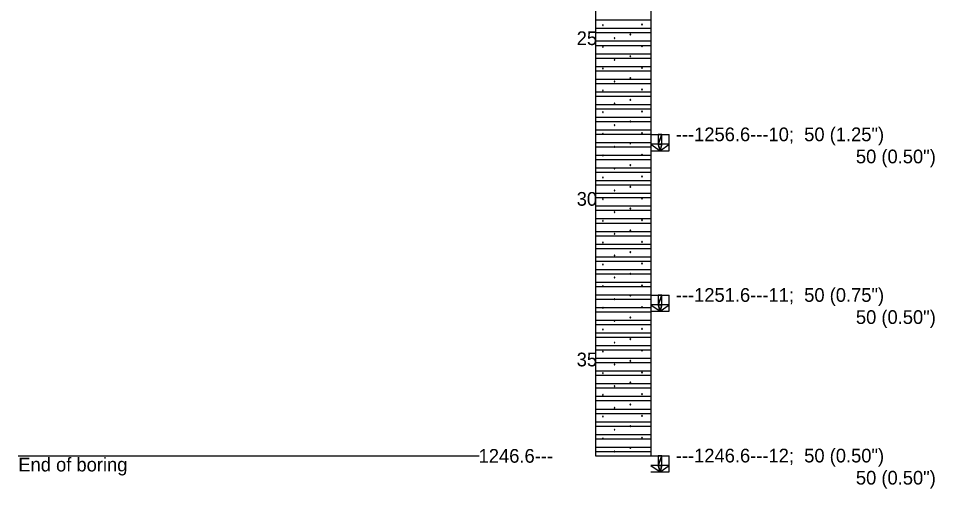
# Model space of a CAD drawing. Extents: x 7 to 126, y 24 to 56.
# Drawn here: x 69.7 to 77.99, y 38.85 to 43.11 of the extents above; entities that cross this region are included whole.
import ezdxf

# ---------------------------------------------------------------- set-up
doc = ezdxf.new("R2010")
doc.units = 0

msp = doc.modelspace()

# ---------------------------------------------------------------- linework, layer by layer
for points in [[(74.9215, 50.1944), (74.9215, 39.1479)], [(75.4215, 50.1944), (75.4215, 39.1479)], [(74.9215, 43.0925), (75.4215, 43.0925)], [(74.9215, 43.017), (75.4215, 43.017)], [(74.9919, 43.0463), (74.9902, 43.0491), (74.9869, 43.0491), (74.9853, 43.0463), (74.9869, 43.0434), (74.9902, 43.0434), (74.9919, 43.0463)], [(75.3446, 43.0528), (75.343, 43.0557), (75.3397, 43.0557), (75.3381, 43.0528), (75.3397, 43.0499), (75.343, 43.0499), (75.3446, 43.0528)], [(74.9215, 42.9776), (75.4215, 42.9776)], [(75.0965, 42.9284), (75.0949, 42.9312), (75.0916, 42.9312), (75.09, 42.9284), (75.0916, 42.9255), (75.0949, 42.9255), (75.0965, 42.9284)], [(75.2391, 42.9602), (75.2375, 42.9631), (75.2342, 42.9631), (75.2326, 42.9602), (75.2342, 42.9574), (75.2375, 42.9574), (75.2391, 42.9602)], [(74.9215, 42.9022), (75.4215, 42.9022)], [(74.9215, 42.8628), (75.4215, 42.8628)], [(74.9919, 42.8494), (74.9902, 42.8522), (74.9869, 42.8522), (74.9853, 42.8494), (74.9869, 42.8465), (74.9902, 42.8465), (74.9919, 42.8494)], [(75.3446, 42.8559), (75.343, 42.8588), (75.3397, 42.8588), (75.3381, 42.8559), (75.3397, 42.8531), (75.343, 42.8531), (75.3446, 42.8559)], [(74.9215, 42.7873), (75.4215, 42.7873)], [(75.2391, 42.7634), (75.2375, 42.7662), (75.2342, 42.7662), (75.2326, 42.7634), (75.2342, 42.7606), (75.2375, 42.7606), (75.2391, 42.7634)], [(74.9215, 42.748), (75.4215, 42.748)], [(74.9215, 42.6725), (75.4215, 42.6725)], [(75.0965, 42.7315), (75.0949, 42.7344), (75.0916, 42.7344), (75.09, 42.7316), (75.0916, 42.7287), (75.0949, 42.7287), (75.0965, 42.7315)], [(74.9215, 42.6331), (75.4215, 42.6331)], [(74.9919, 42.6526), (74.9902, 42.6554), (74.9869, 42.6554), (74.9853, 42.6526), (74.9869, 42.6497), (74.9902, 42.6497), (74.9919, 42.6526)], [(75.3446, 42.6591), (75.343, 42.662), (75.3397, 42.662), (75.3381, 42.6591), (75.3397, 42.6562), (75.343, 42.6562), (75.3446, 42.6591)], [(74.9215, 42.5577), (75.4215, 42.5577)], [(74.9215, 42.5183), (75.4215, 42.5183)], [(75.0965, 42.5347), (75.0949, 42.5375), (75.0916, 42.5375), (75.09, 42.5347), (75.0916, 42.5318), (75.0949, 42.5318), (75.0965, 42.5347)], [(75.2391, 42.5665), (75.2375, 42.5694), (75.2342, 42.5694), (75.2326, 42.5665), (75.2342, 42.5637), (75.2375, 42.5637), (75.2391, 42.5665)], [(74.9215, 42.4429), (75.4215, 42.4429)], [(74.9919, 42.4557), (74.9902, 42.4585), (74.9869, 42.4585), (74.9853, 42.4557), (74.9869, 42.4528), (74.9902, 42.4528), (74.9919, 42.4557)], [(75.3446, 42.4622), (75.343, 42.4651), (75.3397, 42.4651), (75.3381, 42.4622), (75.3397, 42.4594), (75.343, 42.4594), (75.3446, 42.4622)], [(74.9215, 42.4035), (75.4215, 42.4035)], [(75.0965, 42.3378), (75.0949, 42.3407), (75.0916, 42.3407), (75.09, 42.3379), (75.0916, 42.335), (75.0949, 42.335), (75.0965, 42.3378)], [(75.2391, 42.3697), (75.2375, 42.3725), (75.2342, 42.3725), (75.2326, 42.3697), (75.2342, 42.3669), (75.2375, 42.3669), (75.2391, 42.3697)], [(74.9215, 42.328), (75.4215, 42.328)], [(74.9215, 42.2887), (75.4215, 42.2887)], [(74.9919, 42.2589), (74.9902, 42.2617), (74.9869, 42.2617), (74.9853, 42.2589), (74.9869, 42.256), (74.9902, 42.256), (74.9919, 42.2589)], [(75.3446, 42.2654), (75.343, 42.2682), (75.3397, 42.2682), (75.3381, 42.2654), (75.3397, 42.2625), (75.343, 42.2625), (75.3446, 42.2654)], [(74.9215, 42.2132), (75.4215, 42.2132)], [(74.9215, 42.1738), (75.4215, 42.1738)], [(75.2391, 42.1728), (75.2375, 42.1757), (75.2342, 42.1757), (75.2326, 42.1728), (75.2342, 42.17), (75.2375, 42.17), (75.2391, 42.1728)], [(74.9215, 42.0984), (75.4215, 42.0984)], [(75.0965, 42.141), (75.0949, 42.1438), (75.0916, 42.1438), (75.09, 42.141), (75.0916, 42.1381), (75.0949, 42.1381), (75.0965, 42.141)], [(74.9215, 42.059), (75.4215, 42.059)], [(74.9919, 42.062), (74.9902, 42.0648), (74.9869, 42.0648), (74.9853, 42.062), (74.9869, 42.0591), (74.9902, 42.0591), (74.9919, 42.062)], [(75.3446, 42.0685), (75.343, 42.0714), (75.3397, 42.0714), (75.3381, 42.0685), (75.3397, 42.0657), (75.343, 42.0657), (75.3446, 42.0685)], [(75.4215, 42.0549), (75.5881, 42.0549)], [(75.5881, 41.9095), (75.5881, 42.0549)], [(74.9215, 41.9835), (75.4215, 41.9835)], [(74.9215, 41.9442), (75.4215, 41.9442)], [(75.0965, 41.9441), (75.0949, 41.947), (75.0916, 41.947), (75.09, 41.9442), (75.0916, 41.9413), (75.0949, 41.9413), (75.0965, 41.9441)], [(75.2391, 41.976), (75.2375, 41.9788), (75.2342, 41.9788), (75.2326, 41.976), (75.2342, 41.9732), (75.2375, 41.9732), (75.2391, 41.976)], [(74.9215, 41.8687), (75.4215, 41.8687)], [(74.9919, 41.8652), (74.9902, 41.868), (74.9869, 41.868), (74.9853, 41.8652), (74.9869, 41.8623), (74.9902, 41.8623), (74.9919, 41.8652)], [(75.3446, 41.8717), (75.343, 41.8745), (75.3397, 41.8745), (75.3381, 41.8717), (75.3397, 41.8688), (75.343, 41.8688), (75.3446, 41.8717)], [(75.4215, 41.9095), (75.5881, 41.9095)], [(74.9215, 41.8293), (75.4215, 41.8293)], [(75.2391, 41.7791), (75.2375, 41.782), (75.2342, 41.782), (75.2326, 41.7791), (75.2342, 41.7763), (75.2375, 41.7763), (75.2391, 41.7791)], [(74.9215, 41.7539), (75.4215, 41.7539)], [(74.9215, 41.7145), (75.4215, 41.7145)], [(75.0965, 41.7473), (75.0949, 41.7501), (75.0916, 41.7501), (75.09, 41.7473), (75.0916, 41.7444), (75.0949, 41.7444), (75.0965, 41.7473)], [(75.3446, 41.6748), (75.343, 41.6777), (75.3397, 41.6777), (75.3381, 41.6748), (75.3397, 41.672), (75.343, 41.672), (75.3446, 41.6748)], [(74.9215, 41.6391), (75.4215, 41.6391)], [(74.9215, 41.5997), (75.4215, 41.5997)], [(74.9919, 41.6683), (74.9902, 41.6711), (74.9869, 41.6711), (74.9853, 41.6683), (74.9869, 41.6654), (74.9902, 41.6654), (74.9919, 41.6683)], [(74.9215, 41.5242), (75.4215, 41.5242)], [(75.0965, 41.5504), (75.0949, 41.5533), (75.0916, 41.5533), (75.09, 41.5505), (75.0916, 41.5476), (75.0949, 41.5476), (75.0965, 41.5504)], [(75.2391, 41.5823), (75.2375, 41.5851), (75.2342, 41.5851), (75.2326, 41.5823), (75.2342, 41.5795), (75.2375, 41.5795), (75.2391, 41.5823)], [(74.9215, 41.4849), (75.4215, 41.4849)], [(74.9919, 41.4715), (74.9902, 41.4743), (74.9869, 41.4743), (74.9853, 41.4715), (74.9869, 41.4686), (74.9902, 41.4686), (74.9919, 41.4715)], [(75.3446, 41.478), (75.343, 41.4808), (75.3397, 41.4808), (75.3381, 41.478), (75.3397, 41.4751), (75.343, 41.4751), (75.3446, 41.478)], [(74.9215, 41.4094), (75.4215, 41.4094)], [(74.9215, 41.37), (75.4215, 41.37)], [(75.0965, 41.3536), (75.0949, 41.3564), (75.0916, 41.3564), (75.09, 41.3536), (75.0916, 41.3507), (75.0949, 41.3507), (75.0965, 41.3536)], [(75.2391, 41.3854), (75.2375, 41.3883), (75.2342, 41.3883), (75.2326, 41.3854), (75.2342, 41.3826), (75.2375, 41.3826), (75.2391, 41.3854)], [(74.9215, 41.2946), (75.4215, 41.2946)], [(74.9919, 41.2746), (74.9902, 41.2774), (74.9869, 41.2774), (74.9853, 41.2746), (74.9869, 41.2717), (74.9902, 41.2717), (74.9919, 41.2746)], [(75.3446, 41.2811), (75.343, 41.284), (75.3397, 41.284), (75.3381, 41.2811), (75.3397, 41.2783), (75.343, 41.2783), (75.3446, 41.2811)], [(74.9215, 41.2552), (75.4215, 41.2552)], [(74.9215, 41.1797), (75.4215, 41.1797)], [(75.2391, 41.1886), (75.2375, 41.1914), (75.2342, 41.1914), (75.2326, 41.1886), (75.2342, 41.1858), (75.2375, 41.1858), (75.2391, 41.1886)], [(74.9215, 41.1404), (75.4215, 41.1404)], [(75.0965, 41.1567), (75.0949, 41.1596), (75.0916, 41.1596), (75.09, 41.1568), (75.0916, 41.1539), (75.0949, 41.1539), (75.0965, 41.1567)], [(74.9215, 41.0649), (75.4215, 41.0649)], [(74.9215, 41.0255), (75.4215, 41.0255)], [(74.9919, 41.0778), (74.9902, 41.0806), (74.9869, 41.0806), (74.9853, 41.0778), (74.9869, 41.0749), (74.9902, 41.0749), (74.9919, 41.0778)], [(75.3446, 41.0843), (75.343, 41.0871), (75.3397, 41.0871), (75.3381, 41.0843), (75.3397, 41.0814), (75.343, 41.0814), (75.3446, 41.0843)], [(74.9215, 40.9501), (75.4215, 40.9501)], [(75.0965, 40.9599), (75.0949, 40.9627), (75.0916, 40.9627), (75.09, 40.9599), (75.0916, 40.957), (75.0949, 40.957), (75.0965, 40.9599)], [(75.2391, 40.9917), (75.2375, 40.9946), (75.2342, 40.9946), (75.2326, 40.9917), (75.2342, 40.9889), (75.2375, 40.9889), (75.2391, 40.9917)], [(74.9215, 40.9107), (75.4215, 40.9107)], [(74.9919, 40.8809), (74.9902, 40.8837), (74.9869, 40.8837), (74.9853, 40.8809), (74.9869, 40.878), (74.9902, 40.878), (74.9919, 40.8809)], [(75.3446, 40.8874), (75.343, 40.8903), (75.3397, 40.8903), (75.3381, 40.8874), (75.3397, 40.8846), (75.343, 40.8846), (75.3446, 40.8874)], [(74.9215, 40.8352), (75.4215, 40.8352)], [(74.9215, 40.7959), (75.4215, 40.7959)], [(75.0965, 40.763), (75.0949, 40.7659), (75.0916, 40.7659), (75.09, 40.7631), (75.0916, 40.7602), (75.0949, 40.7602), (75.0965, 40.763)], [(75.2391, 40.7949), (75.2375, 40.7977), (75.2342, 40.7977), (75.2326, 40.7949), (75.2342, 40.7921), (75.2375, 40.7921), (75.2391, 40.7949)], [(74.9215, 40.7204), (75.4215, 40.7204)], [(74.9919, 40.6841), (74.9902, 40.6869), (74.9869, 40.6869), (74.9853, 40.6841), (74.9869, 40.6812), (74.9902, 40.6812), (74.9919, 40.6841)], [(75.3446, 40.6906), (75.343, 40.6934), (75.3397, 40.6934), (75.3381, 40.6906), (75.3397, 40.6877), (75.343, 40.6877), (75.3446, 40.6906)], [(74.9215, 40.681), (75.4215, 40.681)], [(74.9215, 40.6056), (75.4215, 40.6056)], [(75.2391, 40.598), (75.2375, 40.6009), (75.2342, 40.6009), (75.2326, 40.598), (75.2342, 40.5952), (75.2375, 40.5952), (75.2391, 40.598)], [(75.4215, 40.6014), (75.5881, 40.6014)], [(75.5881, 40.456), (75.5881, 40.6014)], [(74.9215, 40.5662), (75.4215, 40.5662)], [(75.0965, 40.5661), (75.0949, 40.569), (75.0916, 40.569), (75.09, 40.5662), (75.0916, 40.5633), (75.0949, 40.5633), (75.0965, 40.5661)], [(74.9215, 40.4908), (75.4215, 40.4908)], [(74.9215, 40.4514), (75.4215, 40.4514)], [(74.9919, 40.4872), (74.9902, 40.49), (74.9869, 40.49), (74.9853, 40.4872), (74.9869, 40.4843), (74.9902, 40.4843), (74.9919, 40.4872)], [(75.3446, 40.4937), (75.343, 40.4966), (75.3397, 40.4966), (75.3381, 40.4937), (75.3397, 40.4909), (75.343, 40.4909), (75.3446, 40.4937)], [(75.4215, 40.456), (75.5881, 40.456)], [(74.9215, 40.3759), (75.4215, 40.3759)], [(75.0965, 40.3693), (75.0949, 40.3722), (75.0916, 40.3722), (75.09, 40.3694), (75.0916, 40.3665), (75.0949, 40.3665), (75.0965, 40.3693)], [(75.2391, 40.4012), (75.2375, 40.404), (75.2342, 40.404), (75.2326, 40.4012), (75.2342, 40.3984), (75.2375, 40.3984), (75.2391, 40.4012)], [(74.9215, 40.3366), (75.4215, 40.3366)], [(74.9919, 40.2904), (74.9902, 40.2932), (74.9869, 40.2932), (74.9853, 40.2904), (74.9869, 40.2875), (74.9902, 40.2875), (74.9919, 40.2904)], [(75.3446, 40.2969), (75.343, 40.2997), (75.3397, 40.2997), (75.3381, 40.2969), (75.3397, 40.294), (75.343, 40.294), (75.3446, 40.2969)], [(74.9215, 40.2611), (75.4215, 40.2611)], [(74.9215, 40.2217), (75.4215, 40.2217)], [(75.2391, 40.2043), (75.2375, 40.2072), (75.2342, 40.2072), (75.2326, 40.2043), (75.2342, 40.2015), (75.2375, 40.2015), (75.2391, 40.2043)], [(74.9215, 40.1463), (75.4215, 40.1463)], [(74.9215, 40.1069), (75.4215, 40.1069)], [(75.0965, 40.1724), (75.0949, 40.1753), (75.0916, 40.1753), (75.09, 40.1725), (75.0916, 40.1696), (75.0949, 40.1696), (75.0965, 40.1724)], [(75.3446, 40.1), (75.343, 40.1029), (75.3397, 40.1029), (75.3381, 40.1), (75.3397, 40.0972), (75.343, 40.0972), (75.3446, 40.1)], [(74.9215, 40.0314), (75.4215, 40.0314)], [(74.9919, 40.0935), (74.9902, 40.0963), (74.9869, 40.0963), (74.9853, 40.0935), (74.9869, 40.0906), (74.9902, 40.0906), (74.9919, 40.0935)], [(74.9215, 39.9921), (75.4215, 39.9921)], [(75.0965, 39.9756), (75.0949, 39.9785), (75.0916, 39.9785), (75.09, 39.9757), (75.0916, 39.9728), (75.0949, 39.9728), (75.0965, 39.9756)], [(75.2391, 40.0075), (75.2375, 40.0103), (75.2342, 40.0103), (75.2326, 40.0075), (75.2342, 40.0047), (75.2375, 40.0047), (75.2391, 40.0075)], [(74.9215, 39.9166), (75.4215, 39.9166)], [(74.9215, 39.8772), (75.4215, 39.8772)], [(74.9919, 39.8967), (74.9902, 39.8995), (74.9869, 39.8995), (74.9853, 39.8967), (74.9869, 39.8938), (74.9902, 39.8938), (74.9919, 39.8967)], [(75.3446, 39.9032), (75.343, 39.906), (75.3397, 39.906), (75.3381, 39.9032), (75.3397, 39.9003), (75.343, 39.9003), (75.3446, 39.9032)], [(74.9215, 39.8018), (75.4215, 39.8018)], [(75.0965, 39.7787), (75.0949, 39.7816), (75.0916, 39.7816), (75.09, 39.7788), (75.0916, 39.7759), (75.0949, 39.7759), (75.0965, 39.7787)], [(75.2391, 39.8106), (75.2375, 39.8135), (75.2342, 39.8135), (75.2326, 39.8106), (75.2342, 39.8078), (75.2375, 39.8078), (75.2391, 39.8106)], [(74.9215, 39.7624), (75.4215, 39.7624)], [(74.9919, 39.6998), (74.9902, 39.7026), (74.9869, 39.7026), (74.9853, 39.6998), (74.9869, 39.6969), (74.9902, 39.6969), (74.9919, 39.6998)], [(75.3446, 39.7063), (75.343, 39.7092), (75.3397, 39.7092), (75.3381, 39.7063), (75.3397, 39.7035), (75.343, 39.7035), (75.3446, 39.7063)], [(74.9215, 39.687), (75.4215, 39.687)], [(74.9215, 39.6476), (75.4215, 39.6476)], [(75.2391, 39.6138), (75.2375, 39.6166), (75.2342, 39.6166), (75.2326, 39.6138), (75.2342, 39.611), (75.2375, 39.611), (75.2391, 39.6138)], [(74.9215, 39.5721), (75.4215, 39.5721)], [(74.9215, 39.5328), (75.4215, 39.5328)], [(75.0965, 39.5819), (75.0949, 39.5848), (75.0916, 39.5848), (75.09, 39.582), (75.0916, 39.5791), (75.0949, 39.5791), (75.0965, 39.5819)], [(74.9215, 39.4573), (75.4215, 39.4573)], [(74.9919, 39.503), (74.9902, 39.5058), (74.9869, 39.5058), (74.9853, 39.503), (74.9869, 39.5001), (74.9902, 39.5001), (74.9919, 39.503)], [(75.3446, 39.5095), (75.343, 39.5123), (75.3397, 39.5123), (75.3381, 39.5095), (75.3397, 39.5066), (75.343, 39.5066), (75.3446, 39.5095)], [(74.9215, 39.4179), (75.4215, 39.4179)], [(75.0965, 39.385), (75.0949, 39.3879), (75.0916, 39.3879), (75.09, 39.3851), (75.0916, 39.3822), (75.0949, 39.3822), (75.0965, 39.385)], [(75.2391, 39.4169), (75.2375, 39.4198), (75.2342, 39.4198), (75.2326, 39.4169), (75.2342, 39.4141), (75.2375, 39.4141), (75.2391, 39.4169)], [(74.9215, 39.3425), (75.4215, 39.3425)], [(74.9215, 39.3031), (75.4215, 39.3031)], [(74.9919, 39.3061), (74.9902, 39.3089), (74.9869, 39.3089), (74.9853, 39.3061), (74.9869, 39.3032), (74.9902, 39.3032), (74.9919, 39.3061)], [(75.3446, 39.3126), (75.343, 39.3155), (75.3397, 39.3155), (75.3381, 39.3126), (75.3397, 39.3098), (75.343, 39.3098), (75.3446, 39.3126)], [(74.9215, 39.2276), (75.4215, 39.2276)], [(75.0965, 39.1882), (75.0949, 39.1911), (75.0916, 39.1911), (75.09, 39.1883), (75.0916, 39.1854), (75.0949, 39.1854), (75.0965, 39.1882)], [(75.2391, 39.2201), (75.2375, 39.2229), (75.2342, 39.2229), (75.2326, 39.2201), (75.2342, 39.2173), (75.2375, 39.2173), (75.2391, 39.2201)], [(69.7024, 39.1479), (73.869, 39.1479)], [(74.9215, 39.1883), (75.4215, 39.1883)], [(74.9215, 39.1479), (75.4215, 39.1479)], [(75.4215, 39.1479), (75.5881, 39.1479)], [(75.5881, 39.0026), (75.5881, 39.1479)], [(75.4215, 39.0026), (75.5881, 39.0026)]]:
    msp.add_lwpolyline(points)
for points in [[(75.4881, 41.9677), (75.5215, 41.9677), (75.5215, 42.0549), (75.4881, 41.9677)], [(75.4881, 41.9677), (75.5215, 42.0549), (75.4881, 42.0549), (75.4881, 41.9677)], [(75.4881, 41.9677), (75.4215, 41.9677), (75.5048, 41.9095), (75.4881, 41.9677)], [(75.4881, 41.9677), (75.5048, 41.9095), (75.5215, 41.9677), (75.4881, 41.9677)], [(75.5048, 41.9095), (75.5881, 41.9677), (75.5215, 41.9677), (75.5048, 41.9095)], [(75.4881, 40.5142), (75.5215, 40.5142), (75.5215, 40.6014), (75.4881, 40.5142)], [(75.4881, 40.5142), (75.5215, 40.6014), (75.4881, 40.6014), (75.4881, 40.5142)], [(75.4881, 40.5142), (75.4215, 40.5142), (75.5048, 40.456), (75.4881, 40.5142)], [(75.4881, 40.5142), (75.5048, 40.456), (75.5215, 40.5142), (75.4881, 40.5142)], [(75.5048, 40.456), (75.5881, 40.5142), (75.5215, 40.5142), (75.5048, 40.456)], [(75.4881, 39.0607), (75.5215, 39.0607), (75.5215, 39.1479), (75.4881, 39.0607)], [(75.4881, 39.0607), (75.5215, 39.1479), (75.4881, 39.1479), (75.4881, 39.0607)], [(75.4881, 39.0607), (75.4215, 39.0607), (75.5048, 39.0026), (75.4881, 39.0607)], [(75.4881, 39.0607), (75.5048, 39.0026), (75.5215, 39.0607), (75.4881, 39.0607)], [(75.5048, 39.0026), (75.5881, 39.0607), (75.5215, 39.0607), (75.5048, 39.0026)]]:
    msp.add_lwpolyline(points, close=True)

# ---------------------------------------------------------------- texts
for s, p in [('25', (74.7511, 42.865)), ('---1256.6---10;  50 (1.25")', (75.6469, 41.9953)), ('50 (0.50")', (77.2756, 41.7953)), ('30', (74.7511, 41.4115)), ('---1251.6---11;  50 (0.75")', (75.6469, 40.5419)), ('50 (0.50")', (77.2756, 40.3419)), ('35', (74.7511, 39.958)), ('1246.6---', (73.8641, 39.0859)), ('---1246.6---12;  50 (0.50")', (75.6469, 39.0884)), ('End of boring', (69.7024, 39.0072)), ('50 (0.50")', (77.2756, 38.8884))]:
    msp.add_text(s, height=0.124).set_placement(p)

doc.saveas('drawing.dxf')
